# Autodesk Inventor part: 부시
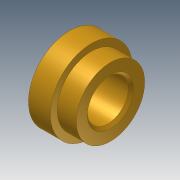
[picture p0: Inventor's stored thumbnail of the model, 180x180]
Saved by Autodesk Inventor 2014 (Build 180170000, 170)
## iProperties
Created: 2011-04
Part Number: 부시
Document SubType Name: Modeling
Designer: 한국산업디자인학원 [http://gmhk.co.kr]
Density: 1 g/cm^3
Material: 일반
Appearance: 황동 - 새틴
Mass: 7.35473 g
Surface Area: 30.152 cm^2
Volume: 7.35473 cm^3
Author: pww
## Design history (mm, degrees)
sketch "스케치1"
  geometry: L1 (0, 0)-(15, 0); L2 (0, 6)-(15, 6); L3 (15, 6)-(15, 12.5); L4 (15, 12.5)-(8, 12.5); L5 (8, 12.5)-(8, 15); L6 (8, 15)-(0, 15); L7 (0, 15)-(0, 6)
  constraints: 14 end point, 4 parallel, 2 vertical alignment, 1 horizontal, 1 perpendicular, 1 vertical
  dimensions: "d0" = 15 distance of L1.start L1.end; "d1" = 12 diameter of L2 L1; "d2" = 25 diameter of L4 L1; "d3" = 8 distance of L5.end L6.end; "d4" = 30 diameter of L6 L1
revolve "회전1" sketch "스케치1" stored, may be unused: angle "d5" = 90 deg
chamfer "모따기1" distance "d6" = 1; stored, may be unused: second distance "d7" = 2, angle "d8" = 45 deg
node "솔리드1"
